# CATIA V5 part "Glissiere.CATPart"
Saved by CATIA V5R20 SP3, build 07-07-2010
Part number: Glissiere
Bounding box of the stored display mesh (mm): x -2 to 2, y -28 to 14, z -2 to 2
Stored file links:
  C:\Documents and Settings\Propriétaire\Mes documents\IFMA\COURS\PROJ IAO\CATIA\Glissiere.CATPart
  C:\Documents and Settings\Propriétaire\Mes documents\IFMA\COURS\PROJ IAO\CATIA\dwalter.CATProduct
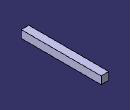
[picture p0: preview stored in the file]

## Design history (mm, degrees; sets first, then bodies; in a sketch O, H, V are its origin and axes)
Set1
  Plane1: linked copy from another document
  Line1: linked copy from another document
  Point1: linked copy from another document
Body1 (main body)
  Sketch1 on Plane1, origin (0, 0, 0), H (0, 1, 0), V (0, 0, 1)
    line L1 (-28, 2) -> (14, 2)
    line L2 (14, 2) -> (14, -2)
    line L3 (14, -2) -> (-28, -2)
    line L4 (-28, -2) -> (-28, 2)
    reference projected line E1 (-10, 0) -> (10, 0) from Line1
    length L2 = 4
    length L1 = 42
    distance V L4 = 28
    horizontal: L1 H, L3 H
    vertical: L2 V, L4 V
    symmetry: L3 L1 E1
  Pad1: profile Sketch1, direction (1, 0, 0), length 2, mirrored extent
